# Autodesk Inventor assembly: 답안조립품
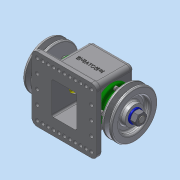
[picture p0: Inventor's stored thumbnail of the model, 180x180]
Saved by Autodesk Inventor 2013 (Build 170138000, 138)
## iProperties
Created: 2018-11
Part Number: 답안조립품
Document SubType Name: Assembly
Designer: dgall
Author: dgall
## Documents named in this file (12)
- C:\Users\dgall\Desktop\481107V1009\답안조립품.iam
- C:\Users\dgall\Desktop\481107V1009\본체.ipt
- C:\Users\dgall\Desktop\481107V1009\베어링 6203.ipt
- C:\Users\dgall\Desktop\481107V1009\축.ipt
- C:\Users\dgall\Desktop\481107V1009\부시.ipt
- C:\Users\dgall\Desktop\481107V1009\오일 실 26 38 8.ipt
- C:\Users\dgall\Desktop\481107V1009\커버.ipt
- C:\Users\dgall\Desktop\481107V1009\볼트 M4.ipt
- C:\Users\dgall\Desktop\481107V1009\키 5x5x12.ipt
- C:\Users\dgall\Desktop\481107V1009\V벨트풀리.ipt
- C:\Users\dgall\Desktop\481107V1009\너트 M12x1.25.ipt
- C:\Users\dgall\Desktop\481107V1009\와셔 12x24.ipt
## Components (2 placed, 1 different names)
1. V벨트풀리:1
2. V벨트풀리:2
